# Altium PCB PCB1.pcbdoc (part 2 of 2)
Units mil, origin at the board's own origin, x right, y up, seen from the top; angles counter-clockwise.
Board outline 5175 x 2060 mil, 4 copper layers (Top Layer, Inner1, Inner2, Bottom Layer), stack 62.447 mil thick; 102 components, 59 nets, 316 pads, 177 vias.
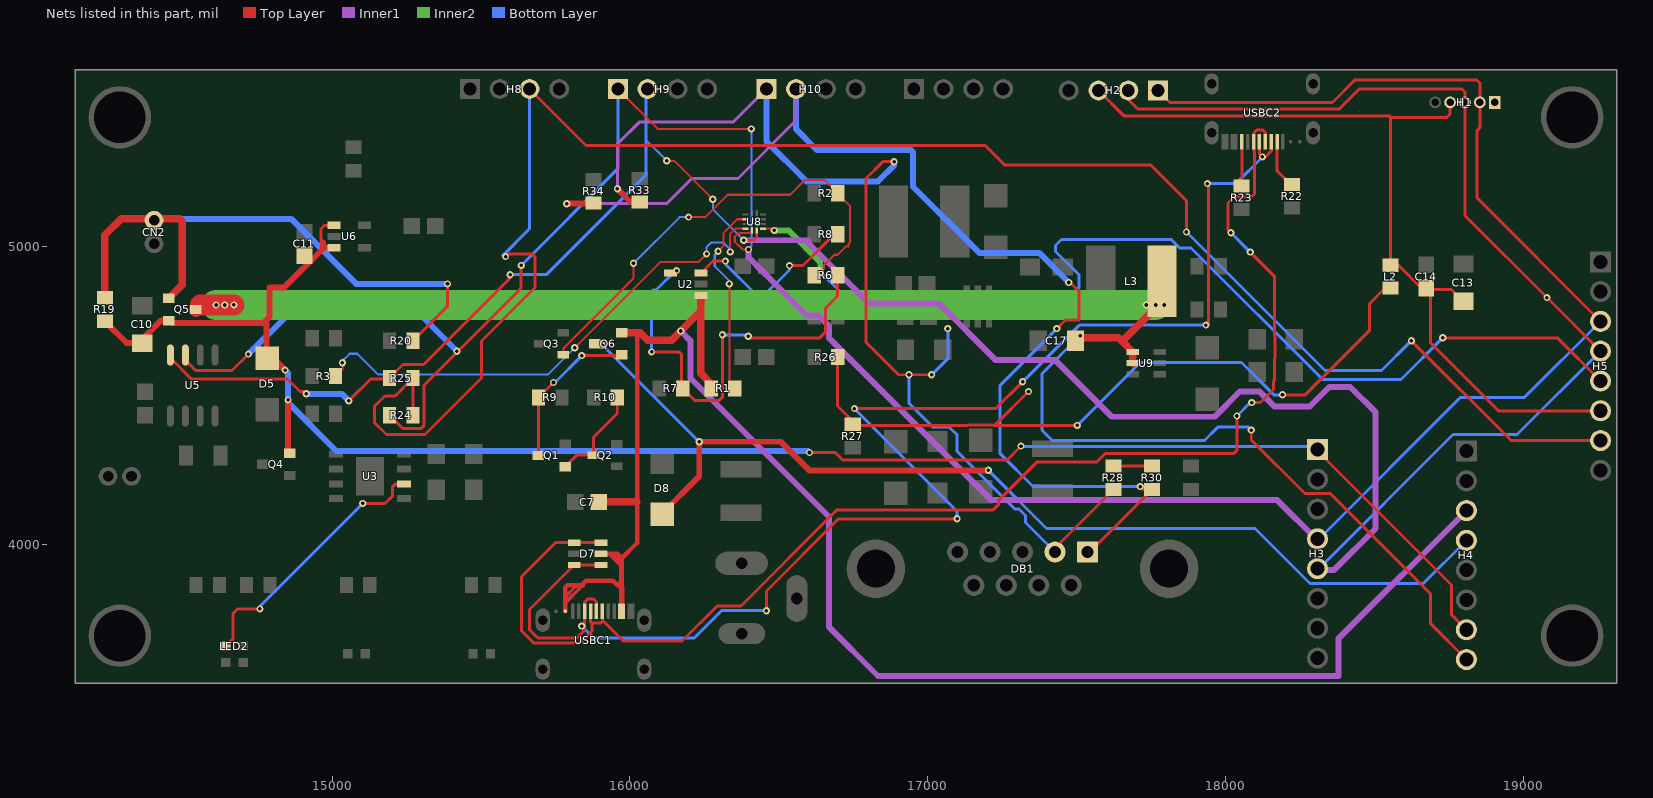
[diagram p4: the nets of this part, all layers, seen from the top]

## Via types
v1: diameter 24.02, hole 12, Top Layer to Bottom Layer, 177 vias

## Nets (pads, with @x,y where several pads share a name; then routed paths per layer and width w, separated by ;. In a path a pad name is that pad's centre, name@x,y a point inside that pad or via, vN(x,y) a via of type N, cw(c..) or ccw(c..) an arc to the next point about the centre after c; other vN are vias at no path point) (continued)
PWR_SW_G: CN2.2 Q5.1 R19.2 R20.1 | length 2088.3
  Top Layer w10: R20.1@15271.87,4685 15387.5,4800.63 v1(15387.5,4876.01)
  Top Layer w25: R19.2@14237.5,4829.37 14237.5,5040 14292.5,5095 14401.87,5095 14402.5,5094.37 14488.13,5094.37 14497.5,5085 14497.5,4872.68 Q5.1@14452.23,4827.4
  Bottom Layer w20: CN2.2@14402.5,5094.37 14862.5,5094.37 15080.86,4876.01 v1(15387.5,4876.01)
Q2_G: Q1.1 Q2.3 R10.2 | length 337.7
  Top Layer w10: Q1.1@15782.77,4262.6 15821.15,4300.97 Q2.3@15877.23,4300.97 15877.22,4360.97 15957.22,4440.97 15957.22,4494.64 R10.2@15956.87,4495
RS485_A: DB1.1 H10.2 R30.1 R34.1 | length 4004.9
  Top Layer w10: v1(17432.5,4725.63) 17461.87,4755 17507.5,4755 17507.5,4850 17476.87,4880.63 v1(17472.5,4880.63) ; DB1.1@17535.61,3975.9 17542.78,3975.9 R30.1@17752.5,4185.63 17722.5,4185.63 v1(17712.5,4195.63)
  Top Layer w20: v1(15787.5,5145) 15875.16,5145 R34.1@15877.89,5147.73
  Inner1 w10: v1(15787.5,5145) 16122.5,5145 16207.5,5230 16362.5,5230 16557.5,5425 H10.2@16557.5,5530
  Bottom Layer w10: v1(17432.5,4725.63) 17242.5,4535.63 17242.5,4305.63 17352.5,4195.63 v1(17712.5,4195.63)
  Bottom Layer w20: H10.2@16557.5,5530 16557.5,5395 16627.5,5325 16942.5,5325 16949.57,5317.93 16949.57,5202.93 17172.5,4980 17373.13,4980 v1(17472.5,4880.63)
RS485_B: DB1.2 H10.1 R28.2 R33.1 | length 3753.1
  Top Layer w10: v1(16886.56,5285.9) 16848.4,5285.9 16792.5,5230 16792.5,4680 16901.6,4570.9 v1(16936.56,4570.9) v1(17012.5,4570.9) ; DB1.2@17426.55,3975.9 17426.56,3989.68 R28.2@17622.5,4185.63
  Top Layer w20: v1(15957.5,5195) 16001.87,5150.63 R33.1@16032.5,5150.63
  Inner1 w10: v1(15957.5,5195) 15957.5,5345 16032.5,5420 16347.5,5420 H10.1@16457.5,5530
  Bottom Layer w10: v1(16936.56,4570.9) 16936.56,4475.17 17015.89,4395.84 17070.49,4395.84 17098.04,4368.29 17098.04,4313.69 17291.74,4120 17305.88,4120 17327.5,4098.37 17327.5,4074.96 DB1.2@17426.55,3975.9 ; v1(17012.5,4570.9) 17066.56,4624.96 v1(17066.56,4725.9)
  Bottom Layer w20: H10.1@16457.5,5530 16457.5,5355 16592.5,5220 16832.5,5220 16886.56,5274.06 v1(16886.56,5285.9)
SCL: H1.3 H2.2 H3.5 H5.4 H9.2 R25.1 U5.4 U8.8 | length 9488.2
  Top Layer w7.09: v1(16123.13,5288.99) 16149.14,5288.99 v1(16277.95,5160.18) ; v1(16381.98,5022.35) 16415.48,5022.35 16425.37,5032.24 U8.8@16425.37,5055.47
  Top Layer w10: U5.4@14457.5,4637.37 14457.5,4626.93 14527.5,4556.93 14850.57,4556.93 14892.5,4515 14905.5,4515 v1(14913.57,4506.93) ; v1(15056.22,4483.35) 15129.79,4556.93 15190.06,4556.93 R25.1@15193.13,4560 15238.13,4605 15307.5,4605 15589.5,4887 15589.5,4887.73 15597.66,4895.89 v1(15597.66,4906.64) ; H2.2@17672.5,5525 17672.5,5495 17704.5,5463 18380.5,5463 18447.5,5530 18792.5,5530 18802.5,5520 H1.3@18802.5,5485 18802.5,5105 v1(19077.5,4830) H5.4@19257.5,4650
  Inner1 w20: v1(16381.98,5022.35) 16597.29,5022.35 16598.57,5021.07 ; 16592.5,5020 16802.5,4810 17037.5,4810 17227.5,4620 17427.5,4620 17617.5,4430 17962.5,4430 18047.5,4515 18112.5,4515 18162.5,4465 18282.5,4465 18347.5,4530 18417.5,4530 18502.5,4445 18502.5,4055 18362.5,3915 H3.5@18307.5,3915
  Bottom Layer w7.09: 16053.13,5360 16123.13,5290 v1(16123.13,5288.99) ; v1(16277.95,5160.18) 16277.95,5126.38 v1(16381.98,5022.35)
  Bottom Layer w10: v1(15597.66,4906.64) 15719.14,4906.64 16053.13,5240.63 16053.13,5360 16053.13,5523.96 H9.2@16059.17,5530 ; H3.5@18307.5,3915 18762.5,4370 18977.5,4370 H5.4@19257.5,4650
  Bottom Layer w20: v1(14913.57,4506.93) 15032.64,4506.93 v1(15056.22,4483.35)
SDA: H1.2 H2.1 H3.4 H5.3 H9.1 R24.1 U5.3 U8.7 | length 9385.5
  Top Layer w7.09: H9.1@15959.17,5530 16093.16,5396.01 v1(16407.23,5396.01) ; v1(16397.74,4991.39) 16377.96,4991.39 16351.75,5017.6 16351.75,5034.25 16362.5,5045 16369.91,5045 16371.81,5046.9 16402.28,5046.9 16408.46,5053.08 16408.46,5054.3 U8.7@16409.63,5055.47
  Top Layer w10: U5.3@14507.5,4637.37 14507.5,4620 14542.5,4585 14664.17,4585 v1(14719.17,4640) ; R24.1@15193.13,4435 15238.13,4390 15297.5,4390 15309.17,4401.67 15309.17,4536.67 15634.87,4862.37 v1(15634.87,4937.74) ; H2.1@17772.5,5525 17812.5,5485 18357.5,5485 18432.5,5560 18842.5,5560 18852.5,5550 H1.2@18852.5,5485 18852.5,5400 18842.5,5390 18842.5,5165 H5.3@19257.5,4750
  Inner1 w20: v1(16397.74,4991.39) 16397.74,4964.76 16450.67,4911.83 16451.08,4911.83 16455.49,4907.42 16455.67,4907.42 16473.24,4889.84 16473.24,4889.26 16592.5,4770 16632.5,4770 16667.5,4735 16667.5,4695 17212.5,4150 18172.5,4150 H3.4@18307.5,4015
  Bottom Layer w7.09: v1(16397.74,4991.39) 16407.23,5000.88 v1(16407.23,5396.01)
  Bottom Layer w10: v1(15634.87,4937.74) 15959.17,5262.03 H9.1@15959.17,5530 ; H3.4@18313.13,4015 18307.5,4015 18787.5,4495 19002.5,4495 H5.3@19257.5,4750
  Bottom Layer w20: v1(14719.17,4640) 14854.17,4775 15294.17,4775 v1(15419.17,4650)
SENS_PWR: C13.1 C14.2 H1.4 H2.3 H5.6 L2.2 | length 2871.9
  Top Layer w10: H2.3@17572.5,5525 17657.5,5440 18549.16,5440 18554.16,5435 ; C14.2@18672.5,4860.63 18656.87,4860.63 18579.46,4938.04 L2.2@18552.5,4938.04 18552.5,5433.34 18554.16,5435 ; H1.4@18752.5,5475 18752.5,5445 18742.5,5435 18554.16,5435 ; C13.1@18797.5,4817.3 18757.5,4857.3 18687.5,4857.3 18687.5,4677.3 18914.8,4450 H5.6@19257.5,4450
SENS_SEL: L2.1 R26.2 R27.2 | length 2536
  Top Layer w10: R26.2@16696.87,4630 16696.87,4465.72 16761.38,4401.21 17133.33,4401.21 cw(c17138.13,4390.21) 17138.13,4402.21 17216.87,4402.21 cw(c17216.87,4390.21) 17221.67,4401.21 17500.78,4401.21 v1(17501.14,4400.84) ; 17227.5,4404.37 v1(17337.5,4514.37) ; v1(18190.04,4503.71) 18266.21,4503.71 18482.5,4720 18482.5,4810 18534.46,4861.96 L2.1@18552.5,4861.96
  Bottom Layer w10: v1(17501.14,4400.84) 17712.26,4611.96 18052.5,4611.96 18160.76,4503.71 v1(18190.04,4503.71)
SINK_G: Q1.3 Q6.1 R9.1 | length 534.1
  Top Layer w10: Q1.3@15692.23,4300 15692.23,4494.09 R9.1@15693.13,4495 v1(15743.13,4545) ; v1(15838.13,4635) 15970.17,4635 Q6.1@15972.77,4637.6
  Bottom Layer w10: v1(15743.13,4545) 15748.13,4545 v1(15838.13,4635)
SRC_EN_N: R6.2 R7.2 U2.4 | length 1461
  Top Layer w10: v1(16072.5,4647.49) 16165.01,4647.49 16172.5,4640 16172.5,4529.37 R7.2@16176.87,4525 16216.87,4485 16299.71,4485 16309.94,4495.23 v1(16309.94,4705) ; v1(16396.87,4700) 16401.87,4695 16626.56,4694.94 ; 16626.63,4695 16636.87,4695 16656.87,4715 16656.87,4795 16696.87,4835 R6.2@16696.87,4905
  Bottom Layer w10: v1(16072.5,4647.49) 16072.5,4850.08 16077.42,4855 16087.5,4855 v1@16152.5,4920 ; v1(16309.94,4705) 16391.87,4705 v1(16396.87,4700)
  other v1: 16156.4,4920.27
STDBY_N: LED2.1 U3.6 | length 897.7
  Top Layer w10: LED2.1@14643.01,3659.99 14668.01,3685 14668.01,3770.51 14682.5,3785 v1(14758.01,3785) ; v1(15103.01,4139.03) 15177.41,4139.03 15203.38,4165 15203.38,4195 15213.38,4205 U3.6@15242,4205
  Bottom Layer w10: v1(14758.01,3785) 14758.01,3794.03 v1(15103.01,4139.03)
SYS: C10.2 C11.2 D5.1 H3.1 H4.7 Q4.2 Q5.2 R19.1 U6.1 U6.3 | length 5983.3
  Top Layer w10: 14969.57,5014.36 14962.5,5021.43 14962.5,5060 14974.89,5072.39 U6.1@15006.32,5072.39 ; v1(16602.5,4310.01) 16689.1,4310.01 16714.11,4285 17265.88,4285 v1(17312.49,4331.61) ; H3.1@18307.5,4315 18757.5,3865 18757.5,3765 H4.7@18807.5,3715
  Top Layer w20: R19.1@14237.5,4750.63 14310.83,4677.3 14349.8,4677.3 14425.1,4752.6 Q5.2@14452.23,4752.6 14460.46,4744.36 14769.57,4744.36 14779.57,4754.36 ; v1(14842.5,4586.61) 14802.5,4626.61 D5.1@14782.5,4626.61 14779.57,4629.54 14779.57,4754.36 ; v1(14852.5,4486.61) 14852.5,4312.68 Q4.2@14857.77,4307.4 ; 14969.57,5000.22 14972.18,4997.61 U6.3@15006.32,4997.61 ; 14969.57,5014.36 14969.57,4994.36 14839.57,4864.36 14789.57,4864.36 14789.57,4764.36 14779.57,4754.36
  Bottom Layer w10: v1(17312.49,4331.61) 17314.11,4330 18292.5,4330 H3.1@18307.5,4315
  Bottom Layer w20: v1(14842.5,4586.61) 14852.5,4576.61 v1(14852.5,4486.61) 14852.5,4476.61 15014.11,4315 16597.5,4315 v1(16602.5,4310.01)
SYS_SW: C17.1 H4.8 L3.1 Q5.3 U9.4 U9.5 | length 6011.1
  Top Layer w10: C17.1@17503.24,4695 v1(17510.71,4702.48) ; v1(18085.2,4385) 18085.2,4352.3 18265.5,4172 18350.5,4172 18687.5,3835 18687.5,3735 H4.8@18807.5,3615
  Top Layer w25: C17.1@17495.2,4695 17639.66,4695 17651.75,4682.91 ; U9.5@17687.26,4610 U9.4@17687.26,4647.4 17651.75,4682.91 ; L3.1@17768.99,4800.14 17651.75,4682.91 ; L3.1@17784.98,4816.14 L3.1@17784.98,4885
  Top Layer w50: Q5.3@14542.77,4790 Q5.3@14557.77,4805
  Top Layer w70: Q5.3@14557.77,4805 v1(14610.71,4805) v1(14639.87,4805) 14670.14,4805 v1(14670.5,4805.36)
  Inner2 w100: v1(14610.71,4805) v1(14639.87,4805) 16408.64,4805 16408.82,4804.81 16467.65,4804.81 16467.83,4805 v1(17732.5,4805) v1(17764.13,4805)
  Bottom Layer w10: v1(17510.71,4702.48) 17382.5,4574.26 17382.5,4385 17416.89,4350.61 17928.11,4350.61 17972.5,4395 18075.2,4395 v1(18085.2,4385)
  other v1: 17792.5,4805
TERM_B: R28.1 R30.2 | length 130
  Top Layer w10: R28.1@17622.5,4264.37 R30.2@17752.5,4264.37
TUSB_INT: R3.2 U8.6 | length 1735.5
  Top Layer w7.09: R3.2@15011.87,4566.67 15034.49,4589.29 v1(15034.49,4611.38) ; v1(15814.49,4661.38) 16103.11,4950 16230.78,4950 v1(16257.16,4976.38) ; v1(16336.27,4983.16) 16336.27,5043.77 16353.88,5061.38 U8.6@16387.97,5061.38
  Bottom Layer w7.09: v1(15034.49,4611.38) 15034.49,4616.99 15058.88,4641.38 15084.49,4641.38 15154.49,4571.38 15724.49,4571.38 v1(15814.49,4661.38) ; v1(16257.16,4976.38) 16257.16,4999.66 16272.5,5015 16312.5,5015 16336.27,4991.23 v1(16336.27,4983.16)
UPDI: H1.1
USB_DN: D7.3 D7.4 USBC1.A7 USBC1.B7 USBC2.A7 USBC2.B7 | length 4881.7
  Top Layer w10: v1(15837.97,3727.41) 15847.97,3737.41 ; USBC1.A7@15887.34,3777.41 15887.97,3778.03 15887.97,3808 15877.97,3818 15857.97,3818 15847.97,3808 USBC1.B7@15847.97,3777.41 15847.97,3737.41 ; D7.4@15902.74,3932.6 D7.3@15812.26,3932.6 15662.5,3782.84 15662.5,3715 15690.09,3687.41 15821.35,3687.41 15847.97,3714.02 15847.97,3737.41 ; v1(16457.97,3778.99) 16457.97,3845.47 16699.9,4087.4 v1(17097.97,4087.4) ; v1(16752.97,4457.4) 17227.97,4457.4 v1(17317.97,4547.4) ; v1(17932.96,4737.4) 17942.5,4746.94 17942.5,5207.87 v1(17937.96,5212.4) ; USBC2.A7@18112.66,5352.59 18112.66,5312.1 v1(18122.66,5302.1) 18132.66,5302.1 18152.66,5322.1 18152.66,5351.96 USBC2.B7@18152.03,5352.59
  Bottom Layer w10: v1(15837.97,3727.41) 15877.97,3687.41 16215.45,3687.41 16307.04,3778.99 v1(16457.97,3778.99) ; v1(16752.97,4457.4) 17097.97,4112.4 v1(17097.97,4087.4) ; v1(17317.97,4547.4) 17507.97,4737.4 v1(17932.96,4737.4) ; v1(17937.96,5212.4) 18032.96,5212.4 v1(18122.66,5302.1)
USB_DP: D7.1 D7.6 USBC1.A6 USBC1.B6 USBC2.A6 USBC2.B6 | length 4692.3
  Top Layer w10: USBC1.A6@15867.66,3777.41 15867.66,3742 15872.26,3737.4 ; D7.6@15902.74,4007.4 D7.1@15812.26,4007.4 15749.9,4007.4 15636.43,3893.93 15636.43,3711.23 15677.66,3670 15832.5,3670 15872.26,3709.76 15872.26,3737.4 ; USBC1.B6@15907.03,3777.41 15907.03,3747.41 ; v1(18017.03,5047.4) 18007.03,5057.4 18007.03,5147.4 18027.03,5167.4 18085.75,5167.4 18095.75,5177.4 18095.75,5321.03 18094.75,5322.03 18094.75,5383.16 18104.78,5393.19 18122.97,5393.19 18132.97,5383.19 18132.97,5353.22 USBC2.A6@18132.34,5352.59 ; v1(18037.03,4432.4) 18037.03,4317.4 18027.03,4307.4 17595.77,4307.4 17565.77,4277.4 17364.9,4277.4 17237.5,4150 17237.5,4135.86 17219.05,4117.4 16694.9,4117.4 16372.5,3795 16292.5,3795 16174.91,3677.41 15977.03,3677.41 15907.03,3747.41 ; v1(18082.03,4982.4) 18162.5,4901.93 18162.5,4706.1 18165.03,4703.57 18165.03,4626.43 18162.5,4623.9 18162.5,4552.88 18160.03,4550.41 18160.03,4521.43 18116.01,4477.4 v1(18087.03,4477.4) ; 15872.26,3737.4 15902.26,3737.4 15907.03,3742.17 15907.03,3747.41
  Bottom Layer w10: v1(18017.03,5047.4) v1(18082.03,4982.4) ; v1(18037.03,4432.4) 18082.03,4477.4 v1(18087.03,4477.4)
USB_ID: H5.5 Q3.1 R2.2 R6.1 U8.9 | length 5100.5
  Top Layer w6: U8.9@16447.03,5061.38 16462.03,5061.38 16478.4,5061.38 v1(16484.25,5055.53)
  Top Layer w7.09: Q3.1@15775.97,4637.6 15776.87,4638.51 15776.87,4660 16011.87,4895 v1(16011.87,4945) ; v1(16196.87,5100) 16252.5,5100 16327.5,5175 16537.5,5175 16587.5,5225 16651.87,5225 R2.2@16696.87,5180 16738.13,5138.74 16738.13,5015 16733.38,5010.25 16733.38,5000.88 16733.25,5000.75 16723.88,5000.75 16696.81,4973.68 16686.18,4973.68 16651.02,4938.52 16651.02,4927.89 R6.1@16628.13,4905
  Top Layer w10: R6.1@16618.13,4905 16628.13,4905 16628.13,4905.93 v1(16638.63,4916.43) ; v1(18728.12,4695) 19112.5,4695 H5.5@19257.5,4550
  Inner2 w20: v1(16484.25,5055.53) 16531.97,5055.53 16638.63,4948.87 v1(16638.63,4916.43)
  Bottom Layer w7.09: v1(16011.87,4945) 16166.87,5100 v1(16196.87,5100)
  Bottom Layer w10: v1(16638.63,4916.43) 16710.06,4845 17487.5,4845 17507.5,4865 17507.5,4905.63 17428.13,4985 17428.13,5005 17448.13,5025 17816.87,5025 17845.17,4996.7 17883.3,4996.7 18325,4555 18588.12,4555 v1(18728.12,4695)
USB_OC_N: R8.2 U2.3 | length 615.4
  Top Layer w10: U2.3@16238.68,4912.4 16278.68,4952.4 v1(16320.34,4952.4) ; v1(16535.34,4937.4) 16580.34,4937.4 16685.34,5042.4 R8.2@16696.77,5042.4
  Bottom Layer w10: v1(16320.34,4952.4) 16320.34,4942.16 16417.5,4845 16457.5,4845 16535.34,4922.84 v1(16535.34,4937.4)
VBUS_DET: R1.2 U8.4 | length 654.8
  Top Layer w7.09: v1(16295.82,4985.33) 16314.49,5003.99 16314.49,5046.99 16360.37,5092.87 U8.4@16387.97,5092.87 ; v1(16333.12,4876.01) 16334.49,4874.64 16334.49,4542.38 R1.2@16351.87,4525
  Bottom Layer w7.09: v1(16295.82,4985.33) 16284.49,4973.99 16284.49,4934.66 16333.12,4886.03 v1(16333.12,4876.01)
VBUS_EXT: C7.1 D7.5 H4.3 Q6.2 R1.1 U2.1 USBC1.A4B9 USBC1.B4A9 | length 6528
  Top Layer w10: 15783.01,3804.17 15838.84,3860 ; 15783.01,3807.41 15835.6,3860 ; 15783.01,3825.51 15817.5,3860 15835.6,3860 ; 15843.84,3865 15838.84,3860 ; 15928.84,3970 15968.84,3930 ; 15938.84,3970 15940.42,3968.42 ; 15942.74,3970 15972.5,3940.24 15972.74,3940 ; 15957,3865 15962,3860 ; 15972,3860.5 15972,3850.74 ; 15972,3940 15940.42,3968.42 ; 15972.74,3850 15972,3850.74 ; 15835.6,3860 15838.84,3860 ; 15940.42,3968.42 15968.84,3940 15968.84,3930 ; 15962,3860 15962.74,3860 15968.84,3853.9 ; 15962,3860 15968.84,3853.16 ; 15968.84,3853.16 15968.84,3853.9 ; 15968.84,3853.16 15968.84,3850 15968.84,3780.56 USBC1.B4A9@15972,3777.41 15972,3850 ; 15968.84,3853.16 15970.42,3851.58 15972,3850 ; 15968.84,3853.9 15972,3850.74 ; 15968.84,3853.9 15968.84,3863.66 15968.84,3930 ; 15972,3850 15972,3850.74
  Top Layer w15: USBC1.A4B9@15783.01,3777.4 15783.01,3804.17 15783.01,3807.41 15783.01,3825.51 15783.01,3857.93 15790.08,3865 15843.84,3865 15843.84,3871.34 15852.5,3880 15942.5,3880 15957.25,3865.25 ; D7.5@15902.74,3970 15903.35,3970.61 15956.89,3970.61 15972.5,3955 ; 15957,3865 15957.25,3865.25 ; USBC1.B4A9@15972,3777.41 15974.57,3779.98 15974.57,3860 15972.5,3860 ; 16023.59,4712.4 16023.59,4144.37 16023.59,4006.09 15972.5,3955 ; 15957.25,3865.25 15962,3870 15962.5,3870 15968.84,3863.66 15972,3860.5 15972.5,3860 ; 15972.5,3860 15972.5,3940.24 15972.5,3955
  Top Layer w25: C7.1@15896.87,4140 15901.24,4144.37 16023.59,4144.37 ; Q6.2@15972.77,4712.4 16023.59,4712.4 16034.47,4712.4 16059.47,4687.4 16139.9,4687.4 v1(16170.18,4717.68) 16237.5,4785 ; R1.1@16273.13,4540 16237.5,4575.63 16237.5,4785 ; 16237.5,4785 16237.5,4820 ; 16237.5,4820 16237.5,4836.41 U2.1@16238.68,4837.6 16238.68,4821.19 16237.5,4820
  Inner1 w20: v1(16170.18,4717.68) 16202.5,4685.37 16202.5,4560 16667.5,4095 16667.5,3725 16832.5,3560 18377.5,3560 18377.5,3685 H4.3@18807.5,4115
  Bottom Layer w10: H4.3@18797.5,4095 H4.3@18807.5,4105
VBUS_SINK: D8.2 H4.4 Q6.3 | length 3613.2
  Top Layer w10: Q6.3@15882.23,4675 15887.5,4669.72 v1(15907.5,4669.72)
  Top Layer w20: D8.2@16107.5,4103.39 16107.5,4104.99 16232.5,4230 v1(16232.5,4346.01) 16506.49,4346.01 16602.2,4250.3 v1(17202.81,4250.3)
  Bottom Layer w10: v1(15907.5,4669.72) 16231.22,4346.01 v1(16232.5,4346.01) ; v1(17202.81,4250.3) 17398.11,4055 18097.5,4055 18282.5,3870 18662.5,3870 H4.4@18807.5,4015
WS_CC1: R22.2 USBC2.A5 | length 168.5
  Top Layer w10: USBC2.A5@18171.71,5352.59 18171.71,5255.95 R22.2@18222.5,5205.15
WS_CC2: R23.2 USBC2.B5 | length 147.9
  Top Layer w10: R23.2@18052.5,5205.15 18053.6,5206.25 USBC2.B5@18053.6,5352.59
WS_VOUT: H5.7 H8.3 R24.2 R25.2 | length 6226.8
  Top Layer w10: R24.2@15271.87,4435 R25.2@15271.87,4560 15211.87,4500 15177.5,4500 15142.5,4465 15142.5,4410 15182.5,4370 15312.21,4370 15501.87,4559.66 15501.87,4684.37 15680.97,4863.47 15680.97,4966.65 15670.97,4976.65 15591.76,4976.65 v1(15582.65,4967.53) ; H8.3@15662.5,5530 15852.5,5340 17192.5,5340 17257.5,5275 17747.5,5275 17867.5,5155 v1(17867.5,5050) ; v1(18622.49,4685) 18957.49,4350 H5.7@19257.5,4350
  Bottom Layer w10: v1(15582.65,4967.53) 15579.55,4970.63 15572.5,4970.63 15662.5,5060.63 H8.3@15662.5,5530 ; v1(17867.5,5050) 18332.5,4585 18522.49,4585 v1(18622.49,4685)
pads on no net: DB1.3 DC1.3 H8.1 U6.4 U8.3 U9.6 USBC1.A8 USBC1.B8 USBC2.A8 USBC2.B8

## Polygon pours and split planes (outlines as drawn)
GND on Top Layer (solid, remove dead copper, pour order 0): 14102.5,5740 14102.5,3480 19387.5,3480 19387.5,5740
GND on Bottom Layer (solid, remove dead copper, pour order 4): 14077.5,5655 14077.5,3390 19407.5,3390 19407.5,5655
5V_IN on Inner1 (solid, remove dead copper): 14077.5,5660 14077.5,3475 19387.5,3475 19387.5,5660
GND on Inner2 (solid, remove dead copper): 14062.5,5655 14062.5,3400 19652.5,3400 19652.5,5655

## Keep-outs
Board Outline Layer:
  region: 14500,5320 ccw(c14500,5270) 14450,5270 ccw(c14500,5270) 14500,5220 14755,5220 ccw(c14755,5270) 14805,5270 ccw(c14755,5270) 14755,5320
  region: 14500,5320 ccw(c14500,5270) 14450,5270 ccw(c14500,5270) 14500,5220 14755,5220 ccw(c14755,5270) 14805,5270 ccw(c14755,5270) 14755,5320
  region: 15285,5320 ccw(c15285,5270) 15235,5270 ccw(c15285,5270) 15285,5220 15540,5220 ccw(c15540,5270) 15590,5270 ccw(c15540,5270) 15540,5320
  region: 15285,5320 ccw(c15285,5270) 15235,5270 ccw(c15285,5270) 15285,5220 15540,5220 ccw(c15540,5270) 15590,5270 ccw(c15540,5270) 15540,5320
  region: 14500,4070 ccw(c14500,4020) 14450,4020 ccw(c14500,4020) 14500,3970 14755,3970 ccw(c14755,4020) 14805,4020 ccw(c14755,4020) 14755,4070
  region: 14500,4070 ccw(c14500,4020) 14450,4020 ccw(c14500,4020) 14500,3970 14755,3970 ccw(c14755,4020) 14805,4020 ccw(c14755,4020) 14755,4070
  region: 15285,4070 ccw(c15285,4020) 15235,4020 ccw(c15285,4020) 15285,3970 15540,3970 ccw(c15540,4020) 15590,4020 ccw(c15540,4020) 15540,4070
  region: 15285,4070 ccw(c15285,4020) 15235,4020 ccw(c15285,4020) 15285,3970 15540,3970 ccw(c15540,4020) 15590,4020 ccw(c15540,4020) 15540,4070
  region: 14642.5,3740 cw(c14617.5,3740) 14592.5,3740 cw(c14617.5,3740)
  circle w0.1: c14617.5,3740 r25
  region: 14642.5,3740 14642.12,3735.66 14640.99,3731.45 14639.15,3727.5 14636.65,3723.93 14633.57,3720.85 14630,3718.35 14626.05,3716.51 14621.84,3715.38 14617.5,3715 14613.16,3715.38 14608.95,3716.51 14605,3718.35 14601.43,3720.85 14598.35,3723.93 14595.85,3727.5 14594.01,3731.45 14592.88,3735.66 14592.5,3740 14592.88,3744.34 14594.01,3748.55 14595.85,3752.5 14598.35,3756.07 14601.43,3759.15 14605,3761.65 14608.95,3763.49 14613.16,3764.62 14617.5,3765 14621.84,3764.62 14626.05,3763.49 14630,3761.65 14633.57,3759.15 14636.65,3756.07 14639.15,3752.5 14640.99,3748.55 14642.12,3744.34
  region: 14742.5,3740 cw(c14717.5,3740) 14692.5,3740 cw(c14717.5,3740)
  circle w0.1: c14717.5,3740 r25
  region: 14742.5,3740 14742.12,3735.66 14740.99,3731.45 14739.15,3727.5 14736.65,3723.93 14733.57,3720.85 14730,3718.35 14726.05,3716.51 14721.84,3715.38 14717.5,3715 14713.16,3715.38 14708.95,3716.51 14705,3718.35 14701.43,3720.85 14698.35,3723.93 14695.85,3727.5 14694.01,3731.45 14692.88,3735.66 14692.5,3740 14692.88,3744.34 14694.01,3748.55 14695.85,3752.5 14698.35,3756.07 14701.43,3759.15 14705,3761.65 14708.95,3763.49 14713.16,3764.62 14717.5,3765 14721.84,3764.62 14726.05,3763.49 14730,3761.65 14733.57,3759.15 14736.65,3756.07 14739.15,3752.5 14740.99,3748.55 14742.12,3744.34
  region: 15060.5,3741.25 cw(c15035.5,3741.25) 15010.5,3741.25 cw(c15035.5,3741.25)
  circle w0.1: c15035.5,3741.25 r25
  region: 15060.5,3741.25 15060.12,3736.91 15058.99,3732.7 15057.15,3728.75 15054.65,3725.18 15051.57,3722.1 15048,3719.6 15044.05,3717.76 15039.84,3716.63 15035.5,3716.25 15031.16,3716.63 15026.95,3717.76 15023,3719.6 15019.43,3722.1 15016.35,3725.18 15013.85,3728.75 15012.01,3732.7 15010.88,3736.91 15010.5,3741.25 15010.88,3745.59 15012.01,3749.8 15013.85,3753.75 15016.35,3757.32 15019.43,3760.4 15023,3762.9 15026.95,3764.74 15031.16,3765.87 15035.5,3766.25 15039.84,3765.87 15044.05,3764.74 15048,3762.9 15051.57,3760.4 15054.65,3757.32 15057.15,3753.75 15058.99,3749.8 15060.12,3745.59
  region: 15160.5,3741.25 cw(c15135.5,3741.25) 15110.5,3741.25 cw(c15135.5,3741.25)
  circle w0.1: c15135.5,3741.25 r25
  region: 15160.5,3741.25 15160.12,3736.91 15158.99,3732.7 15157.15,3728.75 15154.65,3725.18 15151.57,3722.1 15148,3719.6 15144.05,3717.76 15139.84,3716.63 15135.5,3716.25 15131.16,3716.63 15126.95,3717.76 15123,3719.6 15119.43,3722.1 15116.35,3725.18 15113.85,3728.75 15112.01,3732.7 15110.88,3736.91 15110.5,3741.25 15110.88,3745.59 15112.01,3749.8 15113.85,3753.75 15116.35,3757.32 15119.43,3760.4 15123,3762.9 15126.95,3764.74 15131.16,3765.87 15135.5,3766.25 15139.84,3765.87 15144.05,3764.74 15148,3762.9 15151.57,3760.4 15154.65,3757.32 15157.15,3753.75 15158.99,3749.8 15160.12,3745.59
  region: 15476.5,3742.25 cw(c15451.5,3742.25) 15426.5,3742.25 cw(c15451.5,3742.25)
  circle w0.1: c15451.5,3742.25 r25
  region: 15476.5,3742.25 15476.12,3737.91 15474.99,3733.7 15473.15,3729.75 15470.65,3726.18 15467.57,3723.1 15464,3720.6 15460.05,3718.76 15455.84,3717.63 15451.5,3717.25 15447.16,3717.63 15442.95,3718.76 15439,3720.6 15435.43,3723.1 15432.35,3726.18 15429.85,3729.75 15428.01,3733.7 15426.88,3737.91 15426.5,3742.25 15426.88,3746.59 15428.01,3750.8 15429.85,3754.75 15432.35,3758.32 15435.43,3761.4 15439,3763.9 15442.95,3765.74 15447.16,3766.87 15451.5,3767.25 15455.84,3766.87 15460.05,3765.74 15464,3763.9 15467.57,3761.4 15470.65,3758.32 15473.15,3754.75 15474.99,3750.8 15476.12,3746.59
  region: 15576.5,3742.3 cw(c15551.5,3742.3) 15526.5,3742.3 cw(c15551.5,3742.3)
  circle w0.1: c15551.5,3742.3 r25
  region: 15576.5,3742.3 15576.12,3737.96 15574.99,3733.75 15573.15,3729.8 15570.65,3726.23 15567.57,3723.15 15564,3720.65 15560.05,3718.81 15555.84,3717.68 15551.5,3717.3 15547.16,3717.68 15542.95,3718.81 15539,3720.65 15535.43,3723.15 15532.35,3726.23 15529.85,3729.8 15528.01,3733.75 15526.88,3737.96 15526.5,3742.3 15526.88,3746.64 15528.01,3750.85 15529.85,3754.8 15532.35,3758.37 15535.43,3761.45 15539,3763.95 15542.95,3765.79 15547.16,3766.92 15551.5,3767.3 15555.84,3766.92 15560.05,3765.79 15564,3763.95 15567.57,3761.45 15570.65,3758.37 15573.15,3754.8 15574.99,3750.85 15576.12,3746.64
  lines w0.1: 14450,4020 cw(c14500,4020) 14500,4070 14755,4070 cw(c14755,4020) 14805,4020 cw(c14755,4020) 14755,3970 14500,3970 cw(c14500,4020) 14450,4020 ; 14450,5270 cw(c14500,5270) 14500,5320 14755,5320 cw(c14755,5270) 14805,5270 cw(c14755,5270) 14755,5220 14500,5220 cw(c14500,5270) 14450,5270 ; 15235,4020 cw(c15285,4020) 15285,4070 15540,4070 cw(c15540,4020) 15590,4020 cw(c15540,4020) 15540,3970 15285,3970 cw(c15285,4020) 15235,4020 ; 15235,5270 cw(c15285,5270) 15285,5320 15540,5320 cw(c15540,5270) 15590,5270 cw(c15540,5270) 15540,5220 15285,5220 cw(c15285,5270) 15235,5270
  lines w5: 14137.5,3535 14137.5,5595 19312.5,5595 19312.5,3535 14137.5,3535

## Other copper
Top Layer:
  text "BCK" at 19152.5,5120 h60

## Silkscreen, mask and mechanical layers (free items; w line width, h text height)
Top Silkscreen Layer:
  lines w5: 14582.5,3564 14582.5,3704 14760.5,3704 14760.5,3564 14582.5,3564 ; 14997.5,3565.25 14997.5,3705.25 15175.5,3705.25 15175.5,3565.25 14997.5,3565.25 ; 15412.5,3566.25 15412.5,3706.25 15590.5,3706.25 15590.5,3566.25 15412.5,3566.25
  lines w10: 14875,4650.83 15070,4735.83 ; 14875,4735.83 15070,4650.83 ; 15128.29,4762.5 15323.29,4847.5 ; 15128.29,4847.5 15323.29,4762.5 ; 15135,4392.5 15330,4477.5 ; 15135,4477.5 15330,4392.5 ; 15135,4517.5 15330,4602.5 ; 15135,4602.5 15330,4517.5 ; 15135,4642.5 15330,4727.5 ; 15135,4727.5 15330,4642.5 ; 16040,4482.5 16235,4567.5 ; 16040,4567.5 16235,4482.5 ; 16650,4322.5 16845,4407.5 ; 16650,4407.5 16845,4322.5 ; 17525,4182.5 17720,4267.5 ; 17525,4267.5 17720,4182.5 ; 17655,4182.5 17850,4267.5 ; 17655,4267.5 17850,4182.5 ; 18207.5,3680 18402.5,3765 ; 18207.5,3765 18402.5,3680 ; 18210,3777.5 18405,3862.5 ; 18210,3862.5 18405,3777.5
  text "NC" at 15492.5,5389.9 h60 r90
  text "On the Waveshare: battery / switch OFF, battery socket / empty, and both the RS-485 / and CAN termination switches OFF." at 14407.5,5360 h55
  text "SCL" at 16089.17,5354.6 h60 r90
  text "GND" at 15588.7,5351.3 h60 r90
  text "GND" at 15792.5,5351.3 h60 r90
  text "GND" at 17087.97,5351.3 h60 r90
  text "SDA" at 15987.5,5349.7 h60 r90
  text "SCL" at 17697.5,5348 h60 r90
  text "SCL" at 18831.75,5348.1 h45 r90
  text "GND" at 17495,5344.7 h60 r90
  text "SDA" at 17807.5,5345 h60 r90
  text "GND" at 18722.5,5345 h45 r90
  text "SDA" at 18882.12,5345 h45 r90
  text "UPDI" at 18932.5,5335 h45 r90
  text "CANL" at 16190.83,5312.8 h60 r90
  text "CANH" at 16292.5,5309.5 h60 r90
  text "DB_DI1" at 17287.5,5268.1 h60 r90
  text "DB_DI0" at 17182.03,5253.4 h60 r90
  text "DB_DO1" at 16787.5,5247.1 h60 r90
  text "RS485B" at 16482.5,5240.5 h60 r90
  text "RS485A" at 16580.37,5237.3 h60 r90
  text "CHG_EN" at 16678.23,5234.1 h60 r90
  text "DB_COM" at 16982.5,5222.6 h60 r90
  text "SNS_PWR" at 18772.88,5220 h45 r90
  text "OUT TO / SENSOR" at 17622.5,5180 h60
  text "WS_VOUT" at 15684.9,5175.9 h60 r90
  text "SNS_PWR" at 17598.93,5175.7 h60 r90
  text "OUT TO / SENSOR" at 18677.5,5085 h60
  text "BLM21PG221SN1D" at 18462.5,5070 h45 r270
  text "PWR_SW_G" at 14527.5,5055 h60
  text "GND" at 14527.5,4980 h60
  text "SWITCH" at 14317.5,4950 h60 r90
  text "5V_OUT" at 18947.5,4920 h60
  text "3V3_AON" at 18905.7,4816.96 h60
  text "SDA" at 19073,4713.91 h60
  text "SCL" at 19077.9,4622.27 h60
  text "USB_ID" at 18953.9,4530.63 h60
  text "SENS_PWR" at 18868.7,4421.09 h60
  text "WS_VOUT" at 18899.2,4318.04 h60
  text "SYS" at 18122.8,4290 h60
  text "12V_IN" at 18535.5,4285 h60
  text "CHG_EN" at 18952.4,4215 h60
  text "5V_OUT" at 17997.3,4195.8 h60
  text "5V_DC" at 18536.6,4182.66 h60
  text "3V3_AON" at 17955.5,4090.2 h60
  text "VBUS_EXT" at 18422.5,4080.31 h60
  text "GND" at 14367.5,4040 h60 r90
  text "SDA" at 18122.8,3984.6 h60
  text "VBUS_SINK" at 18405,3977.97 h60
  text "BATT +" at 14277.5,3920 h60 r90
  text "SCL" at 18127.7,3890.4 h60
  text "5V_IN" at 18559.4,3875.63 h60
  text "CAN_H" at 18037.5,3796.2 h60
  text "BAT_NODE" at 18419.3,3773.29 h60
  text "492-1510-ND" at 14926.86,3765 h50
  text "492-1510-ND" at 15312.3,3765 h50
  text "492-1510-ND" at 14492.5,3760 h50
  text "CAN_L" at 18040.8,3690.6 h60
  text "SYS" at 18620.3,3670.94 h60
  text "YELLOW" at 15187.5,3670 h45
  text "GREEN" at 14767.5,3640 h45
  text "GND" at 18124.4,3585 h60
  text "SYS_SW" at 18488.3,3580 h60
  text "RED" at 14772.5,3575 h45
  text "GREEN" at 15262.5,3540 h45
  text "CAN NEEDS REROUTED / FOR NOISE" at 18032.5,3540 h50 r90
Bottom Silkscreen Layer:
  text "HOLE: / 173.2mil = 4.4mm" at 14903.25,5485 h50
  text "NC" at 15425,5391.5 h60 r270
  text "GND" at 18677.5,5365 h45 r270
  text "SCL" at 18777.5,5365 h45 r270
  text "SDA" at 18827.5,5360 h45 r270
  text "SCL" at 16021.67,5356.2 h60 r270
  text "GND" at 17442.5,5355 h60 r270
  text "SCL" at 17647.5,5355 h60 r270
  text "GND" at 15521.2,5352.9 h60 r270
  text "GND" at 15725,5352.9 h60 r270
  text "GND" at 17025.47,5352.9 h60 r270
  text "SDA" at 15920,5351.3 h60 r270
  text "SDA" at 17747.5,5350 h60 r270
  text "UPDI" at 18882.5,5350 h45 r270
  text "CANL" at 16123.33,5314.4 h60 r270
  text "CANH" at 16225,5311.1 h60 r270
  text "DB_DI1" at 17225,5269.7 h60 r270
  text "DB_DI0" at 17119.53,5255 h60 r270
  text "DB_DO1" at 16730,5253.7 h60 r270
  text "RS485B" at 16425,5247.1 h60 r270
  text "RS485A" at 16522.87,5243.9 h60 r270
  text "CHG_EN" at 16620.73,5240.7 h60 r270
  text "SNS_PWR" at 18727.5,5235 h45 r270
  text "DB_COM" at 16920,5224.2 h60 r270
  text "SNS_PWR" at 17547.5,5180 h60 r270
  text "WS_VOUT" at 15617.4,5177.5 h60 r270
  text "ZIP TIE BATTERY MOUNTING" at 15573.85,5130 h80
  text "HOLE: / 173.2mil = 4.4mm" at 19267.5,5115 h50
  text "PWR_SW_G" at 14782.5,5055 h60
  text "GND" at 14552.5,4980 h60
  text "SWITCH" at 14287.5,4940 h60 r270
  text "5V_OUT" at 19178.95,4922.5 h60
  text "3V3_AON" at 19178.95,4819.46 h60
  text "SDA" at 19178.95,4716.41 h60
  text "SCL" at 19178.95,4624.77 h60
  text "USB_ID" at 19178.95,4533.13 h60
  text "On the Waveshare: battery / switch OFF, battery socket / empty, and both the RS-485 / and CAN termination switches OFF. /  / BATTERY: / BATT: 1S Li-ion/LiPo ONLY, 3.7V, PROTECTED (PCM) PACK / JST-PH U4: PIN1 = +  CHECK POLARITY - REVERSED CELL KILLS CHARGER NOT U7 /  / WAVESHARE: / DO NOT CONNECT CAN H/L TO WAVESHARE (SCREEN BLINKS) / WAVESHARE SW2 (RS-485 TERM) = OFF / VOUT JUMPER = 3.3V" at 18722.5,4525 h50
  text "SENS_PWR" at 19178.95,4423.59 h60
  text "WS_VOUT" at 19178.95,4320.54 h60
  text "SYS" at 18230.45,4292.5 h60
  text "12V_IN" at 18733.75,4282.5 h60
  text "BATTERY +" at 14217.5,4280 h60 r270
  text "GND" at 14292.5,4280 h60 r270
  text "CHG_EN" at 19178.95,4217.5 h60
  text "10/30/2026 / BEN KASPER / REV 10 / MOST COMPONENTS ARE 0805 OR 1206 /  / CAN BUS HAD PROBLEMS WITH NOISE DURING TESTING. / COULD NOT GET IT TO WORK. COULD NOT FIX WITH SHIELDING /  / DNP OPTIONS / R4/R5  5.1k   CC pull-dn: only if no U8 / R7     100k   device-only (not w/ R6) / R20    0R     always on, no rocker / R24/25 10k    I2C pull-up, VOUT=3.3V only / R27    0R     12V sensor (not w/ R26) / R28+30 0R+120R  RS-485 term, bus end only" at 16422.5,4205 h65
  text "5V_OUT" at 18230.45,4198.3 h60
  text "5V_DC" at 18733.75,4180.16 h60
  text "U4" at 14337.5,4120 h45
  text "BATTERY" at 14142.5,4108.85 h60 r270
  text "3V3_AON" at 18230.45,4092.7 h60
  text "ZIP TIE BATTERY MOUNTING" at 15567.5,4080 h80
  text "VBUS_EXT" at 18733.75,4077.81 h60
  text "RS485 A" at 17502.5,4034.1 h60 r270
  text "DB_D01" at 17177.5,4030.2 h60 r270
  text "RS485 B" at 17392.5,4030 h60 r270
  text "GND" at 17067.5,4025 h60 r270
  text "SDA" at 18230.45,3987.1 h60
  text "VBUS_SINK" at 18733.75,3975.47 h60
  text "SCL" at 18230.45,3892.9 h60
  text "HOLE: / 173.2mil = 4.4mm" at 19308.25,3885 h50
  text "5V_IN" at 18733.75,3873.13 h60
  text "HOLE: / 173.2mil = 4.4mm" at 14622.5,3835 h50
  text "DC JACK 12V" at 16462.5,3835 h60
  text "DB_COM" at 17292.5,3812.8 h60 r90
  text "DB_DI1" at 17397.5,3812.8 h60 r90
  text "DB_DI0" at 17512.5,3812.8 h60 r90
  text "DB9_12V" at 17182.5,3807.8 h60 r90
  text "CAN_H" at 18230.45,3798.7 h60
  text "BAT_NODE" at 18733.75,3770.79 h60
  text "CAN_L" at 18230.45,3693.1 h60
  text "SYS" at 18733.75,3668.44 h60
  text "GND" at 16417.3,3600 h60
  text "GND" at 18230.45,3587.5 h60
  text "SYS_SW" at 18733.75,3577.5 h60
  text "STATUS LEDS (front light pipes) /  / LED1, yellow (EXT PWR): external power is present (USB-C, 12 V barrel or DB9). / LED3, green (ON): the rocker is on and the system is powered. / LED4, red (CHG): the battery is charging. / LED2, green (FULL): charging is finished. A flicker with no battery connected is normal." at 16257.5,3550 h40
Mechanical Layer:
  circle w0.1: c14617.5,3740 r25
  circle w0.1: c14717.5,3740 r25
  circle w0.1: c15035.5,3741.25 r25
  circle w0.1: c15135.5,3741.25 r25
  circle w0.1: c15451.5,3742.25 r25
  circle w0.1: c15551.5,3742.3 r25
  lines w0.1: 14450,4020 cw(c14500,4020) 14500,4070 14755,4070 cw(c14755,4020) 14805,4020 cw(c14755,4020) 14755,3970 14500,3970 cw(c14500,4020) 14450,4020 ; 14450,5270 cw(c14500,5270) 14500,5320 14755,5320 cw(c14755,5270) 14805,5270 cw(c14755,5270) 14755,5220 14500,5220 cw(c14500,5270) 14450,5270 ; 15235,4020 cw(c15285,4020) 15285,4070 15540,4070 cw(c15540,4020) 15590,4020 cw(c15540,4020) 15540,3970 15285,3970 cw(c15285,4020) 15235,4020 ; 15235,5270 cw(c15285,5270) 15285,5320 15540,5320 cw(c15540,5270) 15590,5270 cw(c15540,5270) 15540,5220 15285,5220 cw(c15285,5270) 15235,5270
Document Layer:
  lines w10: 14572.5,3535 14757.5,3535 ; 14575,3435 14760,3435 ; 14995.62,3536.25 15180.62,3536.25 ; 14998.12,3436.25 15183.12,3436.25 ; 15418.75,3537.25 15603.75,3537.25 ; 15421.25,3437.25 15606.25,3437.25

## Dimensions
14137.5,5835 to 19302.5,5835 on Document Layer
13812.5,5595 to 13812.5,3535 on Document Layer
13977.5,5270 to 13977.5,4020 on Document Layer
14837.5,3704 to 14837.5,3740 on Document Layer
15247.5,3704 to 15247.5,3564 on Document Layer
14432.5,3740 to 14432.5,3634 on Document Layer
14232.5,3740 to 14232.5,3535 on Document Layer
13997.5,3740 to 13997.5,3435 on Document Layer
14582.5,3220 to 14997.5,3220 on Document Layer
15175.5,3215 to 15590.5,3215 on Document Layer
14582.5,3000 to 14760.5,3000 on Document Layer
14287.5,5680 to 14137.5,5680 on Document Layer
19162.5,5710 to 19312.5,5710 on Document Layer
